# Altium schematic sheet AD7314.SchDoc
size A
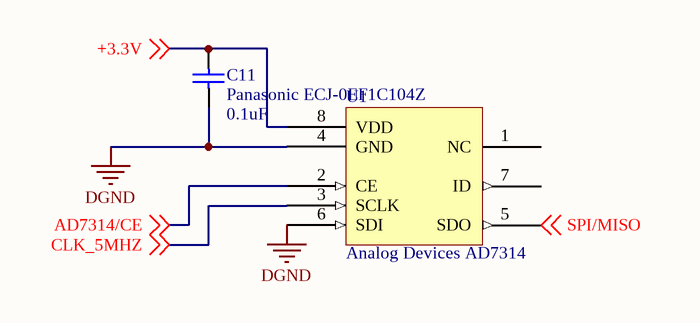
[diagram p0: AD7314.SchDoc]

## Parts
C11  Panasonic ECJ-0EF1C104Z  value 0.1uF  [0402]
U1  Analog Devices AD7314  [RM-8]

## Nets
DGND: C11.1 U1.4(GND) U1.6(SDI)
+3.3V: C11.2 U1.8(VDD) ; off-sheet +3.3V
AD7314/CE: U1.2(CE) ; off-sheet AD7314/CE
CLK_5MHZ: U1.3(SCLK) ; off-sheet CLK_5MHZ
SPI/MISO: U1.5(SDO) ; off-sheet SPI/MISO

Not connected (* = marked no-connect by the designer): U1 1(NC) 7(ID)

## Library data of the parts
C11 = Cap: Capacitor
U1 = AD7314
